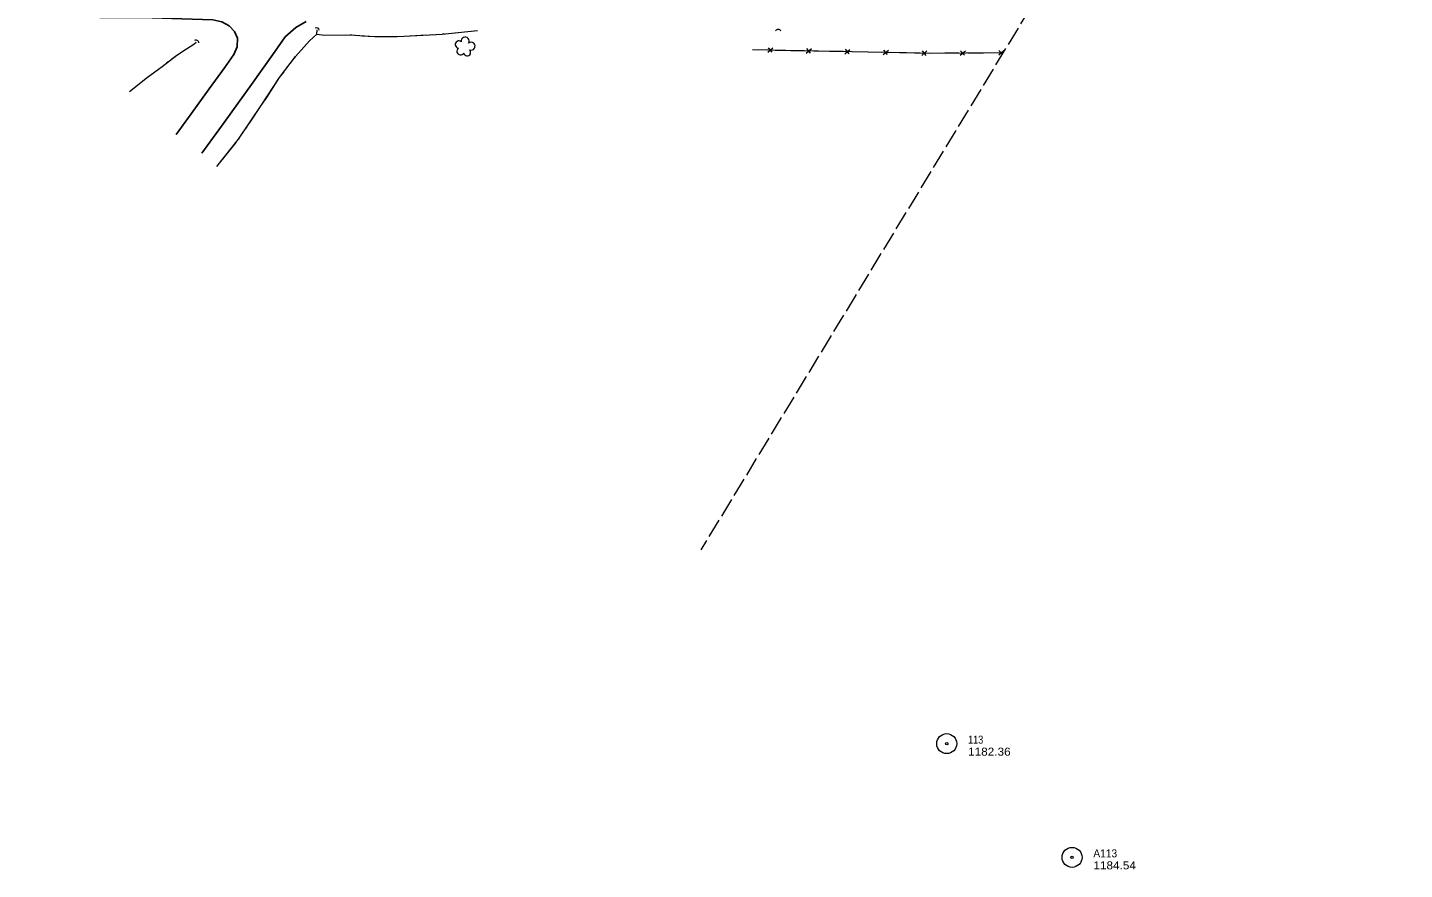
# Model space of a CAD drawing. Extents: x 299912 to 302269, y 50501 to 52727.
# Drawn here: x 300826 to 301859, y 50501 to 51133 of the extents above; entities that cross this region are included whole.
import ezdxf

# ---------------------------------------------------------------- set-up
doc = ezdxf.new("R2010")
doc.units = 0
doc.header["$LTSCALE"] = 2.4
doc.linetypes.add('LONG_DASHED', pattern=[7.5, 6, -1.5])
for name, color, linetype, lineweight in [('11', 7, 'Continuous', 25), ('15', 7, 'Continuous', 13), ('18', 7, 'Continuous', 13), ('19', 7, 'Continuous', 13), ('4', 7, 'Continuous', 13), ('6', 7, 'Continuous', 13)]:
    doc.layers.add(name, color=color, linetype=linetype, lineweight=lineweight)

msp = doc.modelspace()

# ---------------------------------------------------------------- linework, layer by layer
at = {"layer": '11'}
for points in [[(300937.665, 51052.35), (300948.96, 51067.795), (300962.34, 51086.522), (300973.837, 51102.347), (300980.826, 51112.339), (300983.524, 51117.902), (300983.699, 51124.492), (300981.529, 51129.444), (300977.355, 51133.747), (300971.926, 51136.725), (300965.099, 51138.361), (300942.042, 51139.1), (300912.271, 51139.909), (300880.328, 51140.137), (300851.613, 51140.546), (300826.248, 51141.024)], [(300956.806, 51038.121), (300973.648, 51061.343), (300994.116, 51089.721), (301010.137, 51112.387), (301019.41, 51125.479), (301027.487, 51132.484), (301035.101, 51137.124)]]:
    msp.add_lwpolyline(points, dxfattribs=at)
at = {"layer": '15'}
for p, q in [((301369.728, 51115.931), (301380.045, 51115.737)), ((301381.213, 51113.913), (301385.128, 51117.196)), ((301381.453, 51117.265), (301384.288, 51113.925)), ((301386.865, 51115.609), (301398.596, 51115.388)), ((301398.596, 51115.388), (301408.913, 51115.194)), ((301410.081, 51113.37), (301413.996, 51116.653)), ((301410.32, 51116.723), (301413.156, 51113.382)), ((301415.733, 51115.066), (301427.464, 51114.845)), ((301427.464, 51114.845), (301437.781, 51114.651)), ((301438.949, 51112.827), (301442.863, 51116.111)), ((301439.188, 51116.18), (301442.024, 51112.84)), ((301444.601, 51114.523), (301456.331, 51114.303)), ((301456.331, 51114.303), (301466.649, 51114.109)), ((301467.81, 51112.288), (301471.737, 51115.557)), ((301468.062, 51115.64), (301470.884, 51112.289)), ((301473.468, 51113.963), (301485.198, 51113.696)), ((301485.198, 51113.696), (301495.514, 51113.462)), ((301496.675, 51111.633), (301500.603, 51114.902)), ((301496.928, 51114.985), (301499.75, 51111.634)), ((301502.334, 51113.31), (301514.066, 51113.406)), ((301514.066, 51113.406), (301524.385, 51113.491)), ((301525.602, 51111.699), (301529.426, 51115.087)), ((301525.75, 51115.057), (301528.675, 51111.794)), ((301531.206, 51113.547), (301542.938, 51113.643)), ((301542.938, 51113.643), (301553.257, 51113.728)), ((301554.474, 51111.936), (301558.298, 51115.324)), ((301554.622, 51115.294), (301557.056, 51112.58))]:
    msp.add_line(p, q, dxfattribs=at)
msp.add_lwpolyline([(301369.728, 51115.931), (301468.916, 51114.066), (301502.263, 51113.309), (301557.776, 51113.765)], dxfattribs=at)
for centre, radius, start, end in [((301042.881, 51130.225), 2.14, 10.70363, 116.94319), ((301389.174, 51128.371), 2.63, 35.68112, 141.92068), ((300952.316, 51120.698), 2.377, 6.10684, 112.34641)]:
    msp.add_arc(centre, radius, start, end, dxfattribs=at)
at = {"layer": '18'}
for centre, radius, start, end in [((301154.39, 51122.376), 2.974, 328.44813, 189.68202), ((301149.727, 51119.705), 2.777, 51.41902, 259.19202), ((301150.923, 51114.787), 2.783, 128.09604, 329.10709), ((301155.877, 51113.847), 2.611, 190.80419, 48.73679), ((301158.804, 51118.53), 2.975, 246.09895, 129.07222)]:
    msp.add_arc(centre, radius, start, end, dxfattribs=at)
at = {"layer": '19'}
for p, q in [((301068.001, 51127.029), (301069.506, 51126.921)), ((301072.516, 51126.705), (301074.021, 51126.597)), ((301077.03, 51126.381), (301078.535, 51126.273)), ((301128.276, 51127.113), (301129.783, 51127.205)), ((301132.795, 51127.388), (301134.302, 51127.48)), ((301137.314, 51127.675), (301138.815, 51127.827)), ((301141.818, 51128.131), (301163.591, 51130.336)), ((300930.536, 51105.982), (300931.771, 51106.927)), ((301020.527, 51101.902), (301021.497, 51103.179)), ((301023.437, 51105.733), (301024.408, 51107.01)), ((300923.091, 51100.355), (300924.337, 51101.287)), ((300987.275, 51052.812), (300988.172, 51054.14)), ((300989.966, 51056.796), (300990.863, 51058.124)), ((300968.054, 51028.172), (300982.591, 51046.316)), ((300984.584, 51048.827), (300985.481, 51050.156))]:
    msp.add_line(p, q, dxfattribs=at)
for points in [[(300968.054, 51028.172), (300984.482, 51048.676), (301001.509, 51073.885), (301015.212, 51094.907), (301027.177, 51110.655), (301037.661, 51122.617), (301043.155, 51127.565), (301043.429, 51130.816)], [(301029.445, 51113.243), (301037.661, 51122.617), (301043.155, 51127.565), (301043.429, 51130.816)], [(301043.155, 51127.565), (301049.048, 51126.82), (301067.864, 51127.039), (301086.744, 51125.684), (301108.611, 51125.915), (301137.039, 51127.647), (301163.591, 51130.336)], [(301043.155, 51127.565), (301049.048, 51126.82), (301064.984, 51127.005)], [(301081.545, 51126.057), (301086.744, 51125.684), (301103.411, 51125.86)], [(301103.411, 51125.86), (301108.611, 51125.915), (301125.263, 51126.93)], [(300902.816, 51084.623), (300916.202, 51095.202), (300927.148, 51103.39), (300938.212, 51111.854), (300945.466, 51116.623), (300950.858, 51119.913), (300952.749, 51121.584)], [(300934.241, 51108.816), (300938.212, 51111.854), (300945.466, 51116.623), (300950.858, 51119.913), (300952.749, 51121.584)], [(300926.828, 51103.15), (300927.148, 51103.39), (300928.065, 51104.092)], [(301026.348, 51109.564), (301027.177, 51110.655), (301027.331, 51110.831)], [(300902.816, 51084.623), (300916.202, 51095.202), (300920.6, 51098.492)], [(301005.563, 51080.105), (301015.212, 51094.907), (301018.586, 51099.348)], [(300992.657, 51060.78), (301001.509, 51073.885), (301005.563, 51080.105)]]:
    msp.add_lwpolyline(points, dxfattribs=at)
at = {"layer": '4', "linetype": 'LONG_DASHED'}
msp.add_line((301858.628, 51609.011), (301331.18, 50740.757), dxfattribs=at)
at = {"layer": '6'}
for centre, radius in [((301515.438, 50595.209), 7.5), ((301515.438, 50595.209), 0.96), ((301609.389, 50509.893), 7.5), ((301609.389, 50509.893), 0.96)]:
    msp.add_circle(centre, radius, dxfattribs=at)

# ---------------------------------------------------------------- texts
for s, width, p in [('113', 0.85, (301531.438, 50595.209)), ('1182.36', 1.1, (301531.438, 50586.209)), ('A113', 0.95, (301625.389, 50509.893)), ('1184.54', 1.1, (301625.389, 50500.893))]:
    msp.add_text(s, height=6, dxfattribs=dict(at, width=width)).set_placement(p)

doc.saveas('drawing.dxf')
